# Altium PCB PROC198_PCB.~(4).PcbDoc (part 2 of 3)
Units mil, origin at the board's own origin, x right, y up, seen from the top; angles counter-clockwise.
Board outline 858.22 x 1632.74 mil, 4 copper layers (Top Layer, L2_GND1, L3_PWR1, Bottom Layer), stack 54.546 mil thick; 116 components, 64 nets, 355 pads, 1018 vias.
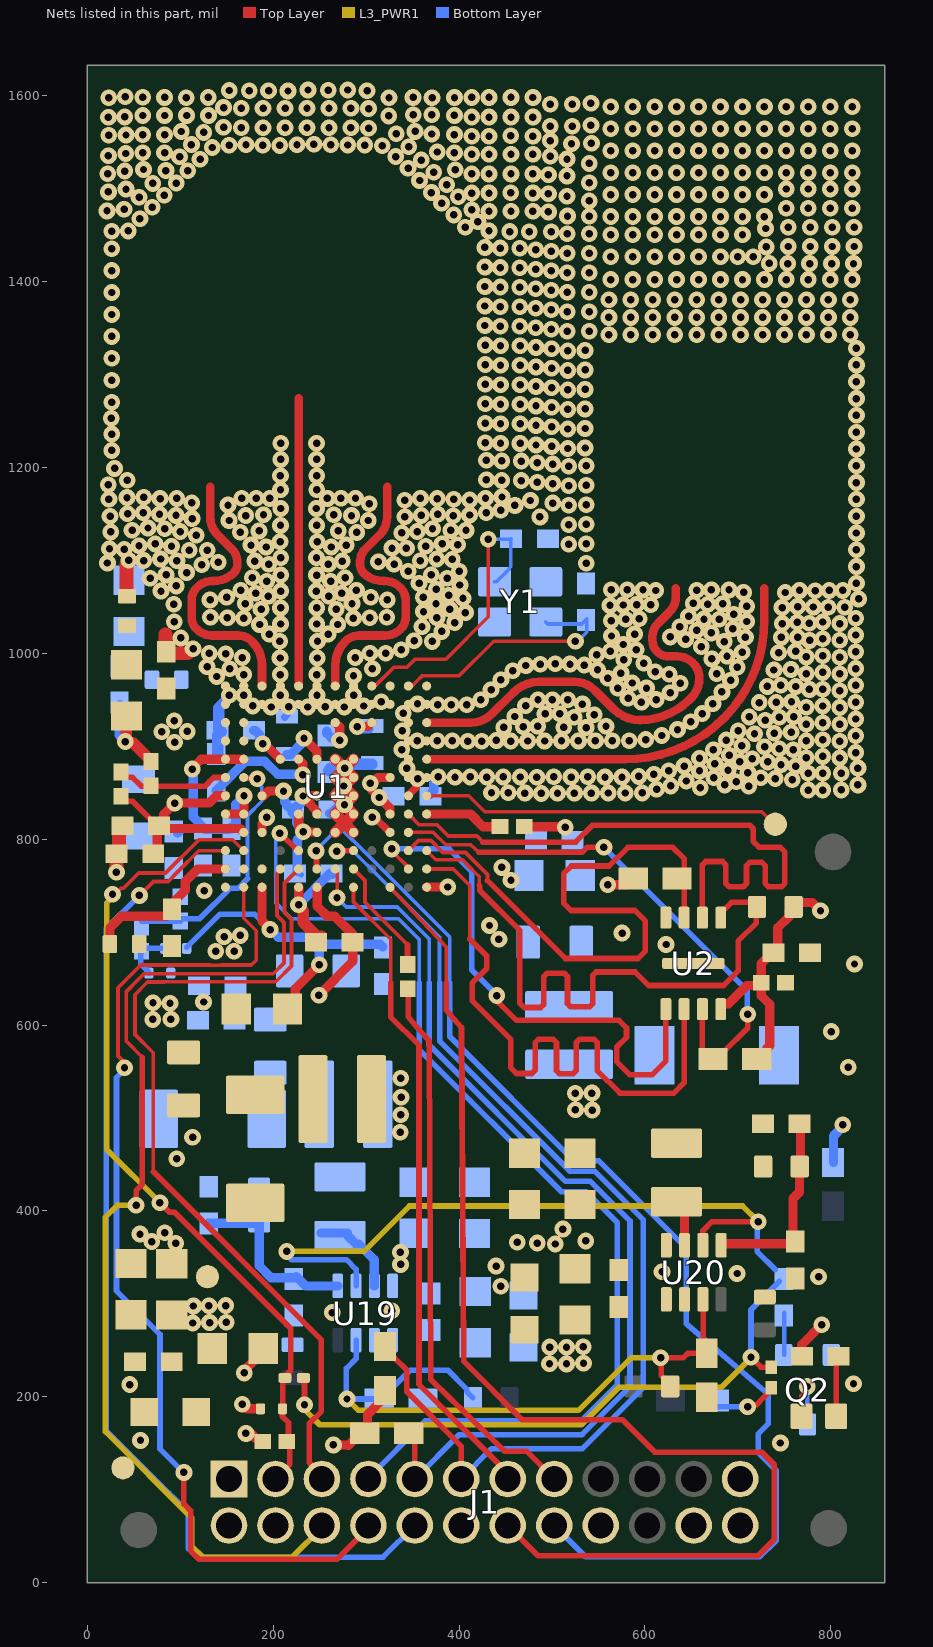
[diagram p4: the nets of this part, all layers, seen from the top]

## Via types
v1: diameter 18, hole 8, Top Layer to Bottom Layer, tented both sides, 1018 vias

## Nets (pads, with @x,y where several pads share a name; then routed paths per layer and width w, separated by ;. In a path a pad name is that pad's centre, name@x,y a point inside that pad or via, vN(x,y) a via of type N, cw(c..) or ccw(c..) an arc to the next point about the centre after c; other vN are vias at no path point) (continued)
GND: C3.2 C4.2 C5.2 C6.2 C7.2 C8.2 C9.1 C10.2 C11.2 C12.2 C13.2 C14.2 C15.2 C16.2 C17.1 C18.2 C19.2 C20.1 C21.2 C22.2 C23.2 C24.1 C25.2 C26.2 C27.1 C28.2 C29.2 C30.2 C31.1 C32.1 C33.1 C34.1 C35.2 C44.2 C45.2 C53.1 C56.2 C60.2 C61.1 C62.2 C66.2 C67.2 C68.1 C69.2 C72.2 C73.2 C74.2 C78.2 C79.1 C101.2 C119.2 C120.2 C128.2 C129.2 J1.12 J1.18 J1.22 J1.23 J1.24 Q2.2 R2.1 R121.1 R131.1 R178.2 R180.2 R238.1 R244.1 TP11.1 U1.A1 U1.A2 U1.A4 U1.A6 U1.A12 U1.B2 U1.B3 U1.B4 U1.B5 U1.B6 U1.B7 U1.C1 U1.C2 U1.D2 U1.E1 U1.E2 U1.E5 U1.E6 U1.E7 U1.E8 U1.E9 U1.F2 U1.F5 U1.F6 U1.F7 U1.F8 U1.F9 U1.G1 U1.G2 U1.H2 U1.H12 U1.J1 U1.J2 U1.K2 U1.K9 U1.L1 U1.L2 U1.M1 U1.M2 U1.M12 U2.4 U2.9 U19.8 U20.8 Y1.2 Y1.4 | length 968.8
  Top Layer w8: U1.B7@345.47,846.73 345.47,847.38 353.45,855.35 353.45,863.22 v1(355.36,865.14)
  Top Layer w10: C25.2@31.54,784.28 C25.2@32.08,784.28 ; v1@109.78,1002.59 112.23,1005.04 v1(113.78,1005.04) ; v1(168.95,225.69) 170.48,227.22 170.48,229.99 192.01,251.52 C60.2@193.96,251.52 ; v1(170.63,160.56) 172.16,159.03 177.78,159.03 181.58,155.23 185.07,155.23 C53.1@188.51,151.8 ; U1.K9@187.99,807.36 187.99,816.34 192.95,821.3 v1(192.95,823.45) ; v1(227.27,729.42) 227.36,729.5 U1.H12@227.36,748.31 ; U1.A12@365.33,748.48 v1@387.84,748.48 ; C31.1@470.17,813.7 470.58,813.29 513.93,813.29 v1(514.34,812.88)
  Top Layer w12: v1(40.81,905.09) 41.96,903.95 48.85,903.95 66.2,886.6 66.2,885.81 C3.2@68.47,883.54 ; v1@41.8,906.09 C23.2@41.8,922.79 ; v1(227.27,729.42) 227.27,727.79 232.32,722.75 232.32,710.38 246.96,695.73 C16.2@251.92,695.73 ; U1.F9@266.73,807.36 266.73,807.41 276.52,817.21 276.52,817.29 ; U1.F8@266.73,827.05 266.73,827.14 276.48,836.89 v1@276.48,837.09 ; U1.F5@266.73,886.1 U1.F5@266.96,886.1 ; U1.F8@266.73,827.05 276.52,817.29 ; v1@275.8,857.32 266.73,866.38 266.91,866.42 v1@276.76,876.26 ; U1.E9@286.42,807.36 276.52,817.29 ; U1.E5@286.42,886.1 286.42,885.92 276.8,876.3 v1(276.98,876.3) 276.98,876.08 286.42,866.65 U1.E6@286.42,866.42 285.77,866.42 276.63,857.28 v1(275.8,857.28) ; U1.F5@266.96,886.1 276.76,876.3 U1.F5@266.96,886.1 ; v1(275.8,857.28) 286.38,846.73 286.32,846.73 276.84,837.25 v1(276.75,837.25) v1@276.48,837.25 ; v1(275.8,857.28) 275.83,856.48 266.73,847.38 U1.F7@266.73,846.73 267,846.73 v1@276.48,837.25 ; v1@276.48,837.09 v1@276.48,837.25 ; v1@276.48,837.09 286.42,827.15 U1.E8@286.42,827.05 286.37,827.05 276.61,817.29 276.52,817.29
  Top Layer w15: v1@30.95,766.9 31.54,767.5 C25.2@31.54,784.28 ; C25.2@34.74,785.5 34.24,786 34.24,811.15 36.58,813.49 C26.2@36.93,813.49 ; C9.1@42.21,1063.01 v1@42.21,1095.41 ; 84.08,1020.07 84.08,1002.55 C19.2@84.89,1001.74 ; C19.2@85.1,1001.53 86.54,1000.09 108.01,1000.09 112.39,1004.47 v1@112.81,1004.05
  Bottom Layer w8: C22.2@212.26,931.48 214.95,934.17 214.95,940.7 v1(216.87,942.61)
  Bottom Layer w10: v1(227.27,729.42) 227.34,729.42 260.98,763.06 C45.2@262.57,763.06 ; C29.2@260.73,827.71 262.7,827.71 269.62,834.63 271.96,834.63 273.05,835.72 276.02,835.72 v1@277.11,834.63 ; v1@275.62,836.12 v1(276.75,837.25) 276.27,837.72 276.27,855.8 v1@276.74,856.27 ; C14.2@366.65,847.59 367.79,847.59 372.64,852.43 372.64,859.93 377.61,864.91 v1(377.61,867.08)
  Bottom Layer w12: C101.2@35.11,944.07 35.11,912.41 40.81,906.72 v1(40.81,905.09) ; C6.2@140.27,889.44 140.27,912.24 144.11,916.09 C4.2@144.21,916.09 ; C4.2@141.35,918.87 141.35,940.97 152.67,952.28 v1(152.67,954.99) ; C5.2@259.39,874.05 261.65,876.31 v1(276.98,876.3) ; C45.2@262.57,763.06 C45.2@262.95,763.06 ; v1(275.8,857.28) 276.09,857.57 276.09,875.41 v1(276.98,876.3) ; v1@276.98,876.92 v1(276.98,876.3) ; v1@278.05,877.64 278.24,877.45 v1@279.75,877.45 ; C18.2@306.34,880.72 283.02,880.72 v1@279.75,877.45 ; v1(276.98,876.3) 278.61,876.3 v1@279.75,877.45
  other v1: 745.83,150.25 57.18,153.02 45.52,213.14 824.43,213.91 263.48,290.6 327.68,292.74 444.88,319 786.88,329.32 699.18,332.64 618.45,334.47 439.82,340.7 337.05,342.47 336.86,355.54 503.52,364.46 462.56,366.16 484.11,365.38 536.45,367.76 511.75,380.47 96.12,456.31 113.26,479.34 818.82,554.53 800.61,593.03 125.05,624.84 825.54,665.74 622.76,686.69 575.37,698.99 125.94,744.68 387.91,748.55 31.29,764.38 488.58,849.24 434.88,850.03 453.01,849.86 470.86,849.61 505.93,849.6 524.17,849.64 542.41,849.68 560.65,849.71 578.89,849.75 597.13,849.79 775.8,852.91 791.25,852.93 811.39,853.05 612.53,853.68 659.65,855.48 627.84,857.33 711.68,856.95 685.82,858.39 829.24,858.46 698.39,861.98 644.57,862.63 758.64,863.94 740.36,865.22 673.97,866.29 724.65,866.18 395.6,866.76 412.01,867.01 429.89,866.89 447.51,867.04 465.86,866.92 483.76,866.66 501.94,867.12 520.53,866.9 538.61,867.11 557.02,866.9 575.3,866.89 593.47,867.55 609.72,869.88 710.86,871.31 775.8,870.99 791.25,871.01 811.39,871.13 625.75,873.76 658.74,873.45 689.41,874.19 343.9,876.16 829.24,876.54 642.12,878.71 762.49,878.69 746.45,880.29 675.31,881.12 702.22,883.27 732.04,883.2 658.74,887.03 715.35,886.71 773.5,887.68 809.52,887.43 791.25,889.09 690.69,890.39 826.94,893.23 673.73,896.34 759.61,896.14 338.31,896.49 744.64,897.22 728.78,899.38 704.37,900.7 354.88,905.81 376.59,905.82 392.56,905.82 409.33,905.42 424.5,905.42 440.21,906.29 455.51,905.65 473.75,905.69 491.99,905.72 510.23,905.76 528.47,905.8 546.71,905.83 564.95,905.87 583.19,905.91 773.5,905.76 809.52,905.51 600.77,907.23 687.4,906.66 791.25,907.17 826.94,911.31 617.99,911.6 717.94,913.62 739.06,913.99 757.26,915.25 338.87,916.53 700.44,916.75 635.04,918 448.04,920.33 536.66,920.15 469.04,920.99 512.58,920.45 484.47,921.54 558.1,921.65 773.5,923.84 809.52,923.59 791.25,925.25 649.38,926.41 729.53,928.1 826.94,929.39 523.88,931.19 744.65,931.14 459.98,932.06 712.13,931.61 760.12,931.88 545.34,933.89 492.58,934.84 508.49,935.02 661.65,935.18 340.08,935.61 197.68,942.3 237.05,942.3 276.42,942.3 773.5,941.92 809.52,941.67 256.24,942.61 297.51,943.34 791.25,943.33 177.9,943.39 471.55,943.68 376.85,944.57 391.72,944.66 408.39,944.72 355.3,945.55 532.71,945.47 673.15,945.68 596.25,947.32 722.88,947.03 741.3,947.21 316.27,947.79 757.71,947.85 826.94,947.47 423.34,950 484.93,950.04 500.47,950.19 516.99,950.05 612.17,950.25 581.89,951.79 168.39,955.06 207.76,955.06 247.13,955.06 286.5,955.06 627.05,957.61 682.83,958.49 809.52,959.75 434.43,960.91 777.03,961.18 791.25,961.41 570.88,962.52 601.71,962.65 731.79,964.41 762.36,964.36 746.22,965.82 826.94,965.55 586.34,968.14 638.06,967.81 692.15,970.85 445.07,971.59 560.2,973.31 139.2,975.13 286.43,975.74 168.27,977.16 207.64,977.16 247.01,977.16 626.28,977.49 677.37,978.14 773.5,978.08 809.52,977.83 574.15,978.79 611,980.27 791.25,979.49 457.76,981.39 548.97,982.14 738.81,982.12 757.11,982.64 153.37,983.54 306.77,983.36 826.94,983.63 699.24,985.12 128.8,985.46 471.95,986.95 534.75,987.44 487.24,988.41 503.61,988.77 519.37,988.46 598.85,989.37 577.33,993.17 672.09,993.99 207.39,994.97 247.33,994.97 166.55,995.48 288.17,995.48 773.5,996.16 809.52,995.91 688.35,996.83 791.25,997.57 548.05,998.4 131.26,999.93 149.07,999.6 304.04,1000.05 321.12,1000.13 704.57,1001.11 743.8,1000.54 562.69,1002.29 762.13,1002.26 826.94,1001.71 337.78,1003.92 590.48,1003.92 660.5,1007.26 576.78,1009.52 207.02,1012.9 247.7,1012.9 371.16,1012.84 685.28,1012.67 351.57,1013.55 777.15,1013.92 809.52,1013.99 643.78,1014.95 791.25,1015.65 100.58,1016.59 708.17,1017.29 746.84,1017.15 627.19,1017.67 764.29,1017.36 564.06,1018.67 826.94,1019.79 195.72,1020.79 259,1020.79 588.9,1020.73 671.3,1022.03 381.5,1023.62 655.66,1024.63 694.7,1026.39 360.12,1028.74 637.6,1028.67 185.3,1031.07 269.42,1031.07 207.94,1031.57 246.78,1031.57 747.91,1032.01 809.52,1032.07 395.49,1033.09 776.8,1032.38 93.38,1034.1 709.45,1034.27 763.85,1033.52 791.25,1033.73 563.78,1035.2 579.23,1036.84 594.02,1037.28 663.57,1036.91 679.99,1036.59 150.78,1038.2 168.41,1037.83 286.31,1037.83 303.94,1038.2 826.94,1037.87 132.47,1038.76 322.25,1038.76 376.16,1038.48 646.99,1039.99 695.72,1042 406.85,1043.87 361.72,1044.97 186.98,1047.39 267.74,1047.39 390.21,1047.44 207.93,1048.87 246.79,1048.87 747.62,1049.29 764.29,1050.32 781.3,1049.89 797.24,1049.68 815.12,1049.68 709.53,1050.76 562.44,1051.59 576.46,1052.01 93.08,1052.81 590.98,1052.5 606.27,1052.38 667.84,1052.86 683.55,1053.23 169.96,1053.53 284.76,1053.53 375.19,1053.5 651.87,1053.76 132.04,1057.5 322.68,1057.5 404.26,1059.31 829.91,1058.61 149.82,1060.49 304.9,1060.49 361.6,1060.35 194.88,1061.61 259.84,1061.61 388.76,1062.58 181.19,1064.59 273.53,1064.59 706.17,1065.58 751.06,1065.51 79.24,1067.03 208.2,1067.04 246.52,1067.04 165.17,1067.95 289.55,1067.95 563.63,1068.32 581,1068.32 597.93,1068.24 611.68,1067.65 655.91,1067.77 671.59,1068.24 690.49,1068.24 766.35,1067.68 783.23,1067.5 798.32,1067.68 812.87,1067.68 375.67,1068.76 95.81,1072.58 400.97,1073.58 356.99,1075.31 827.61,1075.3 193.02,1077.68 261.7,1077.68 67.52,1080.77 387.2,1080.77 177.39,1081.42 277.33,1081.42 208.06,1084.27 246.66,1084.27 84.69,1084.4 370.03,1084.4 106.79,1086.97 400.34,1088.3 345.43,1088.45 827.61,1093.38 123.17,1095.24 195.3,1095.81 259.42,1095.81 330.06,1095.98 21.57,1097.24 536.84,1096.98 140.99,1098.09 180.35,1099.3 274.37,1099.3 313.2,1098.54 44.68,1100.34 60.53,1099.87 96.4,1099.55 358.32,1099.55 392.72,1101.06 78.83,1101.57 375.89,1101.57 208.15,1102.8 246.57,1102.8 109.53,1110.86 129.02,1110.91 39.57,1111.87 827.61,1111.46 23.84,1112.48 327.85,1113.31 343.4,1113.02 90.55,1115.3 192.31,1114.45 262.41,1114.45 364.17,1115.3 55.61,1115.91 176.08,1116.51 278.64,1116.51 398.4,1116.82 72.98,1117.73 381.74,1117.73 518.11,1117.44 536.84,1117.98 207.37,1120.11 247.35,1120.11 117.32,1127.24 289.92,1130.13 338.23,1129.57 827.61,1129.54 25.05,1130.63 99.84,1131.06 164.6,1130.46 354.88,1131.06 184.83,1131.75 269.89,1131.75 390.91,1132.32 407.44,1132.32 48.14,1132.47 83.28,1134.08 371.44,1134.08 65.3,1134.89 207.84,1137.7 246.88,1137.7 518.11,1138.44 536.84,1138.98 152.49,1142.96 302.23,1142.96 112.69,1145.02 341.76,1147.05 487,1146.85 24.44,1147.57 170.48,1148.26 284.24,1148.26 393.75,1148.08 827.61,1147.62 95.4,1148.42 189.58,1149.23 265.14,1149.23 359.32,1148.42 411.32,1148.86 43.29,1150.24 77.62,1149.84 377.1,1149.84 60.05,1151.25 429.14,1151.44 444.9,1154.03 208.19,1155.87 246.53,1155.87 460.14,1159.19 151.36,1159.55 518.11,1159.44 536.84,1159.98 303.47,1160.94 112.4,1161.9 500.83,1161.7 341.56,1164.74 411.6,1165.05 476.83,1164.47 23.23,1165.73 394.31,1165.96 827.61,1165.7 78.23,1166.6 96.33,1166.71 166.17,1166.92 181.81,1166.92 196.38,1166.71 258.34,1166.71 272.91,1166.92 288.55,1166.92 358.39,1166.71 376.49,1166.6 428.43,1166.87 42.68,1167.61 60.66,1168.01 446.17,1168.23 207.82,1175.99 246.9,1175.99 518.11,1180.44 536.84,1180.98 22.63,1181.46 500.83,1182.7 484.03,1184.23 827.61,1183.78 42.89,1186.19 445.85,1186.06 466.91,1185.93 429.46,1186.72 207.78,1191.13 246.94,1191.13 29.29,1199.01 518.11,1201.44 536.84,1201.98 827.61,1201.86 500.83,1203.7 484.03,1205.23 445.85,1207.06 466.91,1206.93 429.46,1207.72 208.04,1208.66 246.68,1208.66 26.26,1218.38 827.61,1219.94 516.87,1220.45 535.59,1220.99 499.58,1222.7 482.79,1224.23 208.04,1226.19 246.68,1226.19 444.6,1226.07 465.67,1225.94 428.22,1226.73 26.26,1235.93 827.61,1238.02 516.87,1241.45 535.59,1241.99 499.58,1243.7 482.79,1245.23 444.6,1247.07 465.67,1246.94 428.22,1247.73 25.65,1252.87 827.61,1256.1 516.87,1262.45 535.59,1262.99 499.58,1264.7 482.79,1266.23 444.6,1268.07 465.67,1267.94 428.22,1268.73 26.35,1270.18 827.61,1274.18 516.87,1283.45 535.59,1283.99 499.58,1285.7 482.79,1287.23 444.6,1289.07 465.67,1288.94 428.22,1289.73 827.61,1292.26 26.35,1293.8 516.87,1304.45 535.59,1304.99 499.58,1306.7 482.79,1308.23 444.6,1310.07 465.67,1309.94 827.61,1310.34 428.22,1310.73 26.35,1317.42 516.87,1325.45 535.59,1325.99 499.58,1327.7 482.79,1329.23 827.61,1328.42 444.6,1331.07 465.67,1330.94 428.22,1331.73 26.35,1341.04 561.23,1342.95 584.85,1342.95 608.48,1342.95 632.1,1342.95 655.72,1342.95 679.34,1342.95 702.96,1342.95 726.59,1342.95 750.21,1342.95 773.83,1342.95 797.45,1342.95 821.07,1342.95 516.51,1346.5 540.13,1346.5 499.22,1348.75 482.42,1350.28 444.24,1352.11 465.3,1351.99 427.85,1352.77 561.23,1361.49 584.85,1361.49 608.48,1361.49 632.1,1361.49 655.72,1361.49 679.34,1361.49 702.96,1361.49 726.59,1361.49 750.21,1361.49 773.83,1361.49 797.45,1361.49 821.07,1361.49 26.35,1364.67 516.51,1367.5 540.13,1367.5 499.22,1369.75 482.42,1371.28 444.24,1373.11 465.3,1372.99 427.85,1373.77 561.23,1380.57 584.85,1380.57 608.48,1380.57 632.1,1380.57 655.72,1380.57 679.34,1380.57 702.96,1380.57 726.59,1380.57 750.21,1380.57 773.83,1380.57 797.45,1380.57 821.07,1380.57 26.35,1388.29 516.51,1388.5 540.13,1388.5 499.22,1390.75 482.42,1392.28 444.24,1394.11 465.3,1393.99 427.85,1394.77 563.23,1402.19 586.85,1402.19 610.48,1402.19 634.1,1402.19 657.72,1402.19 681.34,1402.19 704.96,1402.19 728.59,1402.19 752.21,1402.19 775.83,1402.19 799.45,1402.19 823.07,1402.19 516.51,1409.5 540.13,1409.5 26.35,1411.91 499.22,1411.75 482.42,1413.28 444.24,1415.11 465.3,1414.99 427.85,1415.77 733.83,1419.58 753.57,1419.45 777.19,1419.45 800.81,1419.45 824.44,1419.45 563.23,1426.81 586.85,1426.81 610.48,1426.81 634.1,1426.81 657.72,1426.81 681.34,1426.81 699.96,1426.81 716.59,1426.81 516.51,1430.5 540.13,1430.5 499.22,1432.75 482.42,1434.28 26.35,1435.53 444.24,1436.11 465.3,1435.99 427.85,1436.77 730.59,1437.37 754.21,1437.81 777.83,1437.81 801.45,1437.81 825.07,1437.81 563.23,1450.43 586.85,1450.43 610.48,1450.43 634.1,1450.43 657.72,1450.43 681.34,1450.43 704.96,1450.43 516.51,1451.5 540.13,1451.5 26.35,1454.15 454.53,1453.88 475.6,1453.75 499.22,1453.75 44.05,1454.57 432.21,1454.61 729.85,1457.18 406.74,1458.57 754.21,1458.43 777.83,1458.43 801.45,1458.43 825.07,1458.43 420.33,1464.44 56.61,1467.76 563.23,1470.06 586.85,1470.06 610.48,1470.06 634.1,1470.06 657.72,1470.06 681.34,1470.06 704.96,1470.06 728.59,1470.06 516.72,1470.57 540.13,1470.5 394.39,1471.76 496.2,1475 21.15,1476.07 432.24,1475.76 455.86,1475.76 479.48,1475.76 39.51,1477.88 413.52,1477.48 752.21,1479.06 775.83,1479.06 799.45,1479.06 823.07,1479.06 69.8,1480.11 381.2,1484.32 540.13,1486.81 55.63,1490.75 399.01,1491.31 516.12,1492.01 82.78,1492.88 563.23,1493.68 586.85,1493.68 610.48,1493.68 634.1,1493.68 657.72,1493.68 681.34,1493.68 704.96,1493.68 728.59,1493.68 413.62,1495.31 432.24,1495.31 479.48,1495.31 496.2,1494.55 370.26,1495.88 455.48,1495.77 22.7,1496.5 41.58,1499.61 752.21,1499.68 775.83,1499.68 799.45,1499.68 823.07,1499.68 386.71,1504.4 70.4,1505.68 95.55,1506.07 540.13,1506.36 357.49,1508.86 516.12,1513.75 496.2,1515.13 21.92,1516.16 413.62,1515.88 432.24,1515.88 455.86,1515.88 479.48,1515.88 563.23,1517.3 586.85,1517.3 610.48,1517.3 634.1,1517.3 657.72,1517.3 681.34,1517.3 704.96,1517.3 728.59,1517.3 752.21,1517.3 775.83,1517.3 799.45,1517.3 823.07,1517.3 372.83,1517.82 40.29,1519.01 108.11,1519.26 84.56,1519.52 395.88,1520.3 60.43,1520.67 345.14,1522.04 540.13,1527.19 359.28,1530.79 121.3,1531.61 516.12,1531.86 99.23,1534.47 331.95,1534.6 498.24,1534.88 22.7,1535.56 413.62,1537.01 432.24,1537.01 455.86,1537.01 479.48,1537.01 41.32,1537.89 59.51,1538.64 83.14,1538.64 394.98,1538.72 376.41,1539.5 563.23,1540.92 586.85,1540.92 610.48,1540.92 634.1,1540.92 657.72,1540.92 681.34,1540.92 704.96,1540.92 728.59,1540.92 752.21,1540.92 775.83,1540.92 799.45,1540.92 823.07,1540.92 134.27,1544.38 345.81,1545.1 317.42,1546.14 152.5,1546.89 170.71,1547.33 188.77,1546.74 206.97,1546.59 261.87,1547.21 280.08,1547.06 298.42,1546.93 111.98,1547.49 225.61,1547.35 243.81,1547.8 520.99,1548.26 542.48,1548.82 498.24,1551.83 413.62,1556.55 432.24,1556.55 455.48,1557.02 479.48,1556.55 22.96,1557.55 41.58,1557.81 59.51,1558.19 83.14,1558.19 394.98,1558.27 332.3,1559.19 370.58,1558.87 125.22,1560.55 101.01,1561.54 352.66,1561.64 302.64,1565.14 563.23,1564.54 586.85,1564.54 610.48,1564.54 634.1,1564.54 657.72,1564.54 681.34,1564.54 704.96,1564.54 728.59,1564.54 752.21,1564.54 775.83,1564.54 799.45,1564.54 823.07,1564.54 146.62,1566.19 165.52,1565.47 189.14,1565.47 212.76,1565.47 236.38,1565.47 260.01,1565.47 283.63,1565.47 498.14,1567.18 521.77,1567.18 541.87,1568.34 22.7,1576.95 40.29,1577.21 413.62,1577.13 432.24,1577.13 455.86,1577.13 479.48,1577.13 324.39,1578.31 59.51,1578.77 83.14,1578.77 106.76,1578.77 130.38,1578.77 394.98,1578.85 350.76,1579.45 370.58,1579.45 302.64,1586.26 146.62,1587.31 165.52,1586.59 189.14,1586.59 212.76,1586.59 236.38,1586.59 260.01,1586.59 283.63,1586.59 563.23,1588.17 586.85,1588.17 610.48,1588.17 634.1,1588.17 657.72,1588.17 681.34,1588.17 704.96,1588.17 728.59,1588.17 752.21,1588.17 775.83,1588.17 799.45,1588.17 823.07,1588.17 498.14,1590.8 521.77,1590.8 541.87,1591.96 22.96,1597.91 83.14,1598.24 106.41,1597.89 130.22,1598.21 324.59,1598.02 350.53,1598.22 370.91,1598.02 395.09,1598.07 413.62,1598.25 432.24,1598.25 455.86,1598.25 479.48,1598.14 40.81,1598.94 59.51,1598.36 215.94,1605.15 152.82,1605.67 174.29,1605.41 194.99,1605.41 237.41,1606.19 259.14,1605.93 280.35,1606.19 301.05,1605.41
GPADC1: C3.1 R86.2 U1.M6 | length 121
  Top Layer w6: R86.2@39.53,871.67 39.53,868.51 41.48,866.56 48.61,866.56 58.16,857.02 71.99,857.02 72.07,856.94 82.66,856.94 126.38,856.94 135.86,866.42 U1.M6@148.62,866.42
GPADC2: C78.1 R89.2 U1.L6 | length 263.6
  Top Layer w6: U1.L6@168.3,866.42 168.97,865.76 182.04,865.76 v1(182.71,865.09)
  Bottom Layer w4: 172.4,757.43 172.4,825.47 187.78,840.84 187.78,856.23 182.71,861.3 v1(182.71,865.09)
  Bottom Layer w6: R89.2@58.63,711.53 C78.1@100.01,711.53 ; C78.1@100.01,712.16 102.29,714.44 120.88,714.44 153.62,747.19 162.16,747.19 172.4,757.43
INPUT_3V3: C56.1 C60.1 C62.1 C66.1 C67.1 C69.1 C72.1 C73.1 C74.1 J1.1 J1.2 J1.4 L2.1 L7.1 R172.1 U19.1 U19.2 U20.1 U20.2 | length 42.7
  Top Layer w10: R172.1@768.67,243.59 768.67,256.13 v1@790,277.46
  other v1: 497.32,235.55 515.59,235.41 533.89,235.98 497.61,253.55 515.61,253.41 533.6,253.97 790.21,277.42 113.47,279.38 131.52,279.91 149.52,280.2 114.14,297.72 130.8,297.89 148.83,298.19
LVDS_D0_LIN_PHY_RX: J1.7 U1.H10 | length 1169.1
  Top Layer w4: v1(207.18,806.45) v1@207.28,806.45 ; U1.H10@226.05,787.68 U1.H10@227.36,787.68
  Top Layer w6: v1@207.28,806.45 U1.H10@226.05,787.68
  Bottom Layer w4: v1(207.18,806.45) 207.18,802.66 202.87,798.35 202.87,731.34 219.8,714.42 334.9,714.42 357.03,692.29 357.03,645.43
  Bottom Layer w6: J1.7@302.43,111.54 302.43,112.8 363.65,174.02 531.45,174.02 570.21,212.78 570.21,387.43 536.81,420.84 509.98,420.84 357.03,573.79 357.03,645.43
LVDS_D1_XDS_UARTA_RX_CAN_RX: J1.6 U1.J11 | length 1119.2
  Top Layer w4: 59.08,565.44 42,582.53 42,636.15 54.42,648.85 60.88,655.31 61.91,655.32 82.66,655.32 200.16,655.32 211.67,666.83 211.67,710.31 204.17,717.81 204.17,762.91 207.67,766.41 U1.J11@207.67,767.99
  Top Layer w6: v1(52.43,406) 52.43,421.83 59.08,428.48 59.08,565.44
  L3_PWR1 w6: v1(52.43,406) 32.22,406 19.48,393.26 19.48,162.59 112.23,69.84 112.23,39.43 124.25,27.41 220.47,27.41 252.43,59.37 J1.6@252.43,61.54
LVDS_D2_XDS_UARTA_TX_CAN_TX: J1.8 U1.L12 | length 1100.1
  Top Layer w4: v1(39.97,554.13) 39.97,559.67 33,566.65 33,640.17 57.37,664.54 131.84,664.54 131.89,664.49 144.31,664.49 144.36,664.54 176.41,664.54 181.67,669.8 181.67,701.58 168.3,714.95 U1.L12@168.3,748.31
  Top Layer w6: v1(103.89,118.64) 103.89,84.66 111.21,77.34 111.21,34.28 120.44,25.04 254.82,25.04 268.69,25.04 278.5,34.85 302.43,58.78 J1.8@302.43,61.54
  Bottom Layer w6: v1@39.82,551.87 31.35,543.4 31.35,313.99 78.18,267.16 78.18,144 103.54,118.64 v1(103.89,118.64)
LVDS_FRCLK_HOST_CLK_TP: J1.10 U1.M10 | length 1128.8
  Top Layer w4: v1(56.01,739.51) 71.06,754.55 82.66,754.55 86.98,754.55 97.55,765.11 97.55,765.41 119.83,787.68 U1.M10@146.9,787.68
  Top Layer w6: U1.M10@146.9,787.68 U1.M10@148.62,787.68
  Bottom Layer w6: v1(56.01,739.51) 20.35,703.84 20.35,163.24 87.64,95.95 87.98,95.95 91.31,92.63 91.36,92.58 108.73,75.21 108.73,36.76 118.07,27.41 318.3,27.41 J1.10@352.43,61.54
MODE: R3.1 R5.1 R238.2 R244.2 U19.3 U20.3 | length 745.8
  Top Layer w6: R5.1@627.16,211.2 627.16,213.17 617.35,222.98 617.35,241.58 v1(616.8,242.13) 641.47,242.13 646.19,246.85 R244.2@659.06,246.85 ; R244.2@662.59,250.78 U20.3@662.59,304.47 ; R244.2@663.55,254.26 659.06,249.76 663.61,249.76 R244.2@666.52,246.85
  L3_PWR1 w6: v1(279.39,197.6) 291.62,185.37 528.56,185.37 585.42,242.24 v1@616.69,242.24
  Bottom Layer w6: U19.3@289.15,261.03 289.15,240.99 278.68,230.51 278.68,198.31 v1(279.39,197.6) 313.65,197.6 R238.2@314.01,197.23 317.95,197.23 326.76,206.05 326.76,208.12 347.17,228.53 387.9,228.53 408.1,208.33 408.1,205.76 R3.1@414.94,198.92
NetC2_2: C2.2 R1.1 R2.2 U20.5 | length 208.4
  Top Layer w10: U20.5@682.02,363 682.02,363.94 682.93,364.84 R2.2@759.27,364.84 ; R2.2@759.43,365 759.43,413.47 766.34,420.39 R1.1@766.34,447.1 ; R1.1@767.35,448.32 C2.2@767.35,493.2
NetC100_2: C100.2 R119.1 R121.2 U19.5 | length 194.8
  Bottom Layer w10: C100.2@130.45,386.68 R119.1@184.93,386.68 184.93,340.99 197.72,328.2 223.38,328.2 224.68,329.5 234.89,319.3 U19.5@269.47,319.3
NetD3_1: D3.1 Q2.3 | length 75.5
  Top Layer w4.8: D3.1@768.43,179 768.43,201.17 774.79,207.53 v1(774.79,211.07)
  Bottom Layer w4.8: v1(774.79,211.07) 774.79,170.52 Q2.3@774.97,170.35
NetD3_2: D3.2 R172.2 | length 66.1
  Top Layer w6: D3.2@805.84,179 R172.2@805.84,245.07
NetQ2_1: Q2.1 R179.1 | length 45
  Bottom Layer w4.8: Q2.1@749.71,245.47 R179.1@749.71,290.5
NetR67_1: R67.1 R89.1 R131.2 | length 55.2
  Bottom Layer w6: R89.1@58.33,679.47 61.37,682.51 82.66,682.51 R67.1@83.28,682.57 ; R89.1@58.77,678.52 57.59,679.7 57.59,665.45 66.17,656.87 R131.2@66.17,655.89
NetR93_2: R93.2 U1.E11 | length 127.1
  Top Layer w4: U1.E11@286.42,767.99 298.86,755.55 298.86,732.07 344.54,686.4
  Top Layer w6: 344.54,686.4 344.54,665.19 R93.2@344.67,665.07
NetU1_K11: U1.K11
NetU1_L11: U1.L11 | length 1
  Top Layer w6: U1.L11@168.3,767.99 U1.L11@169.34,767.99
PMIC_CLKOUT_LIN_PHY_TX_SOP1: J1.5 U1.H11 | length 910.4
  Top Layer w4: 70.98,442.17 70.98,570.13 51.19,589.91 51.19,632.62 63.42,645.12 64.61,646.3 66.26,646.31 82.66,646.32 202.69,646.54 203.86,647.71 219.67,663.52 219.67,713.63 212.17,721.12 212.17,752.81 U1.H11@227.36,767.99
  Top Layer w6: 70.98,442.17 251.91,261.24 251.91,184.37 238.8,171.27 238.8,129.29 252.43,115.67 J1.5@252.43,111.54
QSPI_CS: R50.2 U1.A10 U2.1 | length 698.5
  Top Layer w4: U1.A10@365.16,787.68 375.02,777.81 403.61,777.81 409.75,771.67 418.59,762.78 421.62,759.75 421.62,750.23 ; U2.1@681.58,715.54 681.58,720.4 U2.1@682.99,721.81 ; R50.2@717.8,731.99 717.94,731.85 R50.2@717.84,731.75
  Top Layer w6: 421.59,750.21 422.3,749.5 422.3,745.01 465.1,702.22 465.1,623.91 470.07,618.93 487.76,618.93 491.28,622.45 491.28,652.29 494.79,655.8 513.19,655.8 516.71,652.29 516.71,623.04 520.22,619.53 540.42,619.53 543.93,623.04 543.93,653.61 547.45,657.13 589.43,657.13 603.93,642.62 684.55,642.62 700.34,658.41 700.34,690.27 719.9,709.84 719.9,726.41 R50.2@720.63,727.13 ; U2.1@682.99,721.81 682.99,722.85 684.49,724.35 685.53,724.35 693.17,731.99 R50.2@717.8,731.99 ; R50.2@717.84,731.75 717.84,728.02 R50.2@718.27,727.59
QSPI_D0: U1.B11 U2.5 | length 587.8
  Top Layer w4: v1(327.65,789.54) 327.65,787.4 345.47,769.58 U1.B11@345.47,767.99
  Top Layer w6: v1@440.29,631.47 442.88,628.88 442.88,623.77 461.67,604.99 572.12,604.99 580.16,596.95 580.16,586.72 569.62,576.17 569.62,560.66 583.52,546.76 607.97,546.76 622.53,561.32 U2.5@622.53,617.11
  Bottom Layer w6: v1(327.65,789.54) 389.15,789.54 413.49,765.21 413.49,659.58 427.64,645.43 440.59,632.48 v1(440.59,631.77)
QSPI_D1: U1.B8 U2.2 | length 694.6
  Top Layer w4: U1.B8@345.47,827.05 356.88,815.64 376.18,815.64 388.44,803.38 419.16,803.38 425.71,796.84
  Top Layer w6: 425.71,796.84 525.39,796.84 543.37,814.82 551.45,814.82 713.1,814.82 716.61,811.3 716.61,797.58 722.74,791.45 745.33,791.45 750.58,786.2 750.58,752.36 747.06,748.85 732.84,748.85 729.33,752.36 729.33,771.58 725.81,775.09 712.83,775.09 709.32,771.58 709.32,752.36 705.8,748.85 690.49,748.85 686.97,752.36 686.97,772.48 683.46,775.99 665.41,775.99 661.9,772.48 U2.2@661.9,715.54
QSPI_D2: R44.1 U1.B10 U2.3 | length 684.8
  Top Layer w4: U1.B10@345.47,787.68 356.39,798.6 369.68,798.6 382.47,785.81 406.93,785.81 430.62,762.12 430.62,755.38
  Top Layer w6: 430.62,755.38 514.38,671.63 592.54,671.63 600.53,679.62 600.53,711.97 589.23,723.27 551.45,723.27 520.53,723.27 512.54,731.26 512.54,762.9 520.79,771.15 551.45,771.15 561.45,771.15 581.58,791.28 629.95,791.28 642.15,779.07 R44.1@642.15,765.21 ; R44.1@634.61,757.67 642.52,749.76 U2.3@642.52,715.84
QSPI_D3: R49.1 U1.B9 U2.7 | length 568.6
  Top Layer w4: U1.B9@345.47,807.36 372.23,807.36 385.6,794 412.33,794 421.03,786.17
  Top Layer w6: 421.03,786.17 532.62,786.17 537.68,791.24 555.87,791.24 v1(555.91,791.28) ; U2.7@661.9,617.11 661.9,571.13 R49.1@664.84,568.19 ; R49.1@681.85,571.43 685.22,571.43 710.61,596.83 v1(710.61,611.8)
  Bottom Layer w6: v1(555.91,791.28) 710.31,636.88 v1@710.31,612.11
QSPI_SCLK: U1.A11 U2.6 | length 694.7
  Top Layer w4: U1.A11@365.16,767.99 393.7,767.99 411.48,750.21 411.48,692.74
  Top Layer w6: 411.48,692.74 429.83,674.39 429.83,660.99 414.03,645.19 414.03,626.25 455.77,584.5 455.77,553.94 461.79,547.92 478.3,547.92 481.82,551.43 481.82,581.14 485.33,584.65 501.34,584.65 504.85,581.14 504.85,550.98 508.37,547.46 522.56,547.46 526.07,550.98 526.07,581.3 529.59,584.82 545.12,584.82 548.64,581.3 548.64,551.24 573.07,526.82 631.11,526.82 642.21,537.92 U2.6@642.21,617.11
RADAR_1P2_RF: C20.2 C24.2 C44.1 C101.1 R8.2 U1.L4 U1.M4
  other v1: 70.49,606.1 89.93,606.32 70.67,624.1 88.94,623.61 93.84,904.23 80.03,915.76 107.46,916 93.63,927.55
RADAR_1V2: C25.1 C26.1 C27.2 C28.1 C29.1 C30.1 C45.1 R7.2 R86.1 U1.C9 U1.G7 U1.G8 U1.G9 U1.H8 U1.K7 U1.L9 U1.M7 | length 512.6
  Top Layer w6: R86.1@36.21,846.23 36.21,846.06 41.48,840.79 48.82,840.79 68.21,821.4 68.21,821.22 73.34,816.09 C26.1@79.4,816.09
  Top Layer w8: v1(306.38,823.68) 308.97,823.68 325.29,807.36 U1.C9@325.79,807.36
  Top Layer w10: C25.1@75.32,781.96 75.32,807.37 C26.1@79.54,811.58 ; C26.1@77.03,814.62 77.32,814.62 82.16,819.46 82.16,826.96 v1(94.11,838.91) 131.1,838.91 138.92,846.73 U1.M7@148.62,846.73 ; C26.1@79.99,813.98 82.03,816.02 82.03,817.66 C26.1@82.66,818.29 ; C26.1@82.66,811.5 164.17,811.5 U1.L9@168.3,807.36 ; U1.K7@187.99,846.73 189.8,846.73 194.91,851.84 v1(211.05,851.84) ; U1.H8@227.36,827.05 227.43,826.98 227.43,812.96 v1(232.38,808.01) 246.97,807.44 U1.G9@247.05,807.36 ; v1@232.2,846.66 246.97,846.66 U1.G7@247.05,846.73 ; v1@232.21,846.65 246.97,829.41 246.97,827.12 U1.G8@247.05,827.05
  Bottom Layer w6: C45.1@226,765.56 C45.1@230.02,761.54
  Bottom Layer w10: v1(211.05,851.84) 212.26,850.63 212.26,840.34 214.36,838.23 214.36,836.87 C29.1@219.12,832.12 ; C29.1@220.48,832.03 220.48,828.58 C29.1@222.34,826.72 ; C29.1@225.12,835.71 226.83,835.71 230.51,839.4 230.51,844.97 v1(232.04,846.51) ; C29.1@225.44,825.87 225.44,817.11 232.38,810.18 v1(232.38,808.01) 232.95,808.01 233.01,807.95 233.01,806.48 226,799.47 C45.1@226,765.56
  other v1: 138.1,679.49 157.93,679.54 147.13,695.07 164.42,696.51
RADAR_1V4_APLL: C22.1 U1.G5 | length 55.9
  Top Layer w10: v1(233.12,908.59) 247.05,894.66 U1.G5@247.05,886.1
  Bottom Layer w10: C22.1@214.52,890.96 218.51,890.96 231.58,904.04 231.58,907.06 v1(233.12,908.59)
RADAR_1V4_SYNTH: C18.1 U1.D3 | length 31.1
  Top Layer w10: v1(290.48,921.2) 301.88,921.2 306.03,925.35 306.03,925.4 U1.D3@306.1,925.47
  Bottom Layer w10: v1(290.48,921.2) 292.64,921.2 295.31,918.54 C18.1@303.01,918.54
RADAR_1V8: C4.1 C5.1 C7.1 C8.1 C10.1 C11.1 C12.1 C13.1 C14.1 C15.1 R6.2 R67.2 U1.C6 U1.C8 U1.F3 U1.J5 U1.K12 U1.L5 U1.L8 U1.M5 U1.M8 | length 788
  Top Layer w10: v1(112.84,875.47) 112.84,876.05 122.7,885.91 168.11,885.91 U1.L5@168.3,886.1 ; U1.M8@148.62,827.05 U1.L8@168.3,827.05 168.55,827.29 v1(168.55,846.54) ; U1.K12@187.99,748.31 187.99,712.06 196.67,703.38 v1(196.67,702.73) ; v1(188.63,902.7) 190.8,902.7 206.47,887.03 206.75,887.03 U1.J5@207.67,886.1 ; C13.1@221.48,608.72 C13.1@221.82,608.38 ; C13.1@223.67,622.72 223.67,639.06 v1(249.68,665.06) ; U1.F3@266.73,925.47 271.46,920.74 v1(271.46,906.53) ; U1.C8@325.79,827.05 325.79,833.33 v1(314.23,844.88) 305.9,853.21 305.9,858.68 v1(304.37,860.21) 306.54,860.21 312.74,866.42 U1.C6@325.79,866.42
  Bottom Layer w4: R67.2@106.9,682.57 R67.2@106.9,683.55
  Bottom Layer w6: R67.2@106.9,683.55 142.71,719.37 180.03,719.37 v1(196.67,702.73)
  Bottom Layer w10: C12.1@97.3,806.78 102.14,811.63 C11.1@125.81,811.63 ; v1(112.84,875.47) 113.86,874.44 113.86,823.84 125.81,811.89 C11.1@125.81,811.63 ; C8.1@155.05,811.2 159.69,815.84 159.69,837.68 v1(168.55,846.54) ; C8.1@155.05,813.17 152.64,810.77 150.2,810.77 126.66,810.77 C11.1@125.81,811.63 ; C4.1@178.7,916.97 180.66,916.97 185.51,912.13 185.51,907.99 188.63,904.86 v1(188.63,902.7) ; v1(196.67,702.73) 197.32,702.73 205.48,694.57 240.41,694.57 249.13,685.85 ; v1(249.68,665.06) 249.68,685.3 249.13,685.85 ; C5.1@257.74,916.04 257.74,914.07 262.58,909.23 266.6,909.23 269.3,906.53 v1(271.46,906.53) ; C7.1@317.79,684.17 314.89,687.06 250.34,687.06 249.13,685.85
  other v1: 442.93,692.31 432.74,707.15 455.92,755.79 446.15,769.64
RADAR_1V_RF_OUT: C9.2 C19.1 C23.1 U1.L3 U1.M3
RADAR_3V3: C16.1 C17.2 C21.1 C34.2 C35.1 L2.2 L7.2 R4.1 R44.2 R49.2 R50.1 R73.1 R74.1 R75.1 R165.2 R175.1 TP9.1 U1.G12 U1.M11 U2.8 | length 877.5
  Top Layer w6: R44.2@591.51,757.75 R44.2@599.21,757.75 ; v1(710.44,189.16) 712.74,191.45 720.24,191.45 723.09,194.3 ; 722.96,194.44 732.57,204.05 732.57,206.41 R175.1@735.87,209.71
  Top Layer w10: C17.2@24.28,687.29 24.28,704.75 36.7,717.17 85.11,717.17 C21.1@93.01,725.07 ; C21.1@91.29,731.04 105.44,745.18 105.44,754.56 118.87,767.99 U1.M11@148.62,767.99 ; v1(166.65,191.86) 171.42,187.09 R165.2@186.42,187.09 ; U1.G12@247.05,748.31 247.32,748.04 247.32,728.01 258.37,716.95 266.33,716.95 285.78,697.5 285.78,696.73 291.16,691.36 285.55,685.76 285.55,668.55 v1(249.23,632.23) ; v1(264.84,148.22) 280.64,148.22 281.05,147.81 R74.1@289.63,156.39 ; R74.1@287.82,167.57 R74.1@294.32,161.07 ; R74.1@298.57,160.76 301.39,163.59 301.39,180.81 315.13,194.56 315.13,199.91 R73.1@321.95,206.72 ; v1(559.9,751.03) 580.73,751.03 R44.2@587.36,757.67 ; U2.8@681.58,617.11 681.58,622.12 682.49,623.03 689.99,623.03 709.53,642.57 C34.2@725.15,642.57 ; R49.2@720.44,563.94 724.96,563.94 731.19,570.16 731.19,574.68 734.28,577.77 734.28,622.47 725.15,631.59 C34.2@725.15,642.57 ; C35.1@730.72,671.8 724.99,666.07 725.15,665.91 C34.2@725.15,645.51 C34.2@725.15,642.57 ; C35.1@742.94,675.11 742.94,704.58 755.16,716.8 755.16,722.29 R50.1@760,727.13 ; R50.1@760,731.85 780.07,731.85 v1(788.91,723.01)
  Bottom Layer w6: R4.1@666.41,190.9 668.01,189.3 v1@710.3,189.3
  Bottom Layer w10: R75.1@802.83,452.49 802.83,480.69 812.75,490.62 v1(812.75,492.67)
  other v1: 95.05,365.26 69.39,367 56.69,375.13 83.18,376.41
RADAR_NRST: C53.2 J1.3 R165.1 R176.1 U1.L10 | length 901.3
  Top Layer w4: v1(27.1,740.75) 29.81,740.75 36.44,747.38 39.25,747.38 55.42,763.55 82.66,763.55 84.01,763.55 120.01,799.54 156.44,799.54 U1.L10@168.3,787.68
  Top Layer w6: v1(78.12,408.96) 88.49,398.6 93.76,398.6 218.86,273.5 218.86,228.52 216.46,226.11 216.46,222.44 214.59,222.44 210.25,218.09 210.25,187.3 R165.1@210.09,187.14 ; J1.3@202.43,111.54 202.43,111.87 217.96,127.39 C53.2@217.96,156.83 ; R165.1@210.04,187.09 210.04,178.52 216.43,172.13 C53.2@216.43,156.83
  L3_PWR1 w6: v1(27.1,740.75) 27.1,737.67 20.66,731.23 20.66,466.42 v1(78.12,408.96)
RADAR_OSC_CLKOUT: TP5.1 U1.A7 | length 390.9
  Top Layer w4: U1.A7@365.16,846.73 410.51,846.73 427.59,829.66 725.66,829.66 TP5.1@742.13,813.19
RADAR_VBGAP: C6.1 U1.H5 | length 130.6
  Top Layer w10: U1.H5@227.22,886.1 231.77,881.56 v1(231.77,869.45)
  Bottom Layer w10: C6.1@138.57,852.48 169.83,883.75 190.84,883.75 204.75,869.84 231.38,869.84 v1(231.77,869.45)
REG_1V2: C61.2 L5.2 R7.1
REG_1V8: C68.2 L6.2 R6.1
REG_OUT_1V2: C100.1 C119.1 C120.1 L1.1 L5.1 L14.2 R119.2
  other v1: 336.67,484.73 337.14,503.4 337.63,522.29 337.37,542.68
REG_OUT_1V8: C2.1 C128.1 C129.1 L6.1 L15.2 R1.2
  other v1: 525.21,508.77 543.21,508.51 524.96,526.76 542.96,526.84
REG_PG: R175.2 R176.2 R179.2 U19.6 U20.6 | length 1448.5
  Top Layer w6: v1@232.14,193.06 v1(233.64,191.56) 233.64,219.13 R176.2@232.51,220.26 ; U20.6@662.34,363 662.34,378.68 672.16,388.51 v1(721.98,388.51) ; v1(714.13,242.61) 724.86,231.88 R175.2@735.75,231.88
  L3_PWR1 w6: v1(214.47,356.45) 297.66,356.45 346.56,405.35 705.14,405.35 v1(721.98,388.51) ; v1@233.5,189.46 233.5,186.53 250.09,169.93 531.74,169.93 572.04,210.23 682.32,210.23 v1@714.13,242.05
  Bottom Layer w6: v1(214.47,356.45) 217.08,350.16 219.68,347.56 278.73,347.56 289.15,337.14 U19.6@289.15,319.3 ; v1(714.13,242.61) 714.13,293.67 R179.2@744.77,324.31 ; v1(721.98,388.51) 720.67,387.21 720.67,356.54 R179.2@740.25,336.96
REG_RF_1V2: C79.2 L1.2 R8.1
RX1: U1.K1 | length 309.6
  Top Layer w9.3: 132.18,1179.36 132.18,1146.86 ccw(c159.62,1146.86) 140.21,1127.45 157.59,1110.08 cw(c139.09,1097.75) 161.22,1095.67 ; 135.19,1077.94 ccw(c135.19,1053.27) 117.75,1070.71 ccw(c131.14,1057.32) 112.2,1057.32 112.2,1038.7 ccw(c129.64,1038.7) 117.31,1026.37 ccw(c134.75,1043.82) 134.75,1019.15 162.11,1019.15 cw(c162.11,997.74) 177.24,1012.88 cw(c151.3,986.93) 187.99,986.93 U1.K1@187.99,964.84 ; 135.19,1077.99 ccw(c136.86,1107.16) 157.52,1086.5 ccw(c148.36,1095.66) 161.32,1095.66
RX2: U1.H1 | length 309.7
  Top Layer w9.3: U1.H1@227.36,964.84 227.36,1274.56
RX3: U1.F1 | length 309.6
  Top Layer w9.3: U1.F1@266.73,964.84 266.73,986.93 cw(c303.42,986.93) 277.48,1012.88 cw(c292.61,997.74) 292.61,1019.15 319.97,1019.15 ccw(c319.97,1043.82) 337.41,1026.37 ccw(c325.08,1038.7) 342.52,1038.7 342.52,1057.32 ccw(c323.58,1057.32) 336.97,1070.71 ccw(c319.53,1053.27) 319.53,1077.94 ; 293.4,1095.66 ccw(c306.36,1095.66) 297.19,1086.5 ccw(c317.86,1107.16) 319.53,1077.99 ; 293.5,1095.67 cw(c315.63,1097.75) 297.13,1110.08 314.51,1127.45 ccw(c295.1,1146.86) 322.54,1146.86 322.54,1179.36
SW2: L14.1 U19.7 | length 98.9
  Bottom Layer w10: L14.1@251.78,376.36 279.96,376.36 279.96,373.52 289.28,364.2 292.12,364.2 308.7,347.62 308.7,319.43 U19.7@308.84,319.3
SW3: L15.1 U20.7 | length 50.5
  Top Layer w10: L15.1@634.01,409.91 642.65,401.27 U20.7@642.65,363
TX1: U1.A3 | length 482
  Top Layer w9.3: U1.A3@365.16,925.47 412.84,925.47 ccw(c412.84,957.22) 435.28,934.77 458.49,957.98 cw(c485.98,930.49) 485.98,969.36 524.34,969.36 cw(c524.34,938.76) 545.98,960.4 566.45,939.93 ccw(c594.71,968.2) 594.71,928.22 ccw(c594.71,1003.56) 647.98,950.29 650.04,952.35 ccw(c629.43,972.97) 658.58,972.97 ccw(c634.83,972.97) 634.83,996.72 625.64,996.72 cw(c625.64,1014.33) 608.02,1014.33 608.02,1017.95 cw(c627.6,1017.95) 613.76,1031.79 626.22,1044.26 ccw(c609.06,1061.42) 633.33,1061.42 633.33,1069.92
TX2: U1.A5 | length 482.9
  Top Layer w9.3: U1.A5@365.16,886.1 578.79,886.1 ccw(c578.79,1035.86) 728.54,1035.86 728.54,1069.92
VPP_1P7: C31.2 U1.A8 | length 80.6
  Top Layer w10: U1.A8@365.16,827.05 412.22,827.05 425.73,813.53 C31.2@440.13,813.53
XDS_DCA_LP_RS232_RX: J1.9 R74.2 U1.F11 | length 1061.3
  Top Layer w4: U1.F11@266.73,767.99 266.73,766.41 269.02,764.13 269.02,737.39 v1(268.67,737.04)
  Top Layer w6: R74.2@345.81,160.76 352.43,154.14 J1.9@352.43,111.54
  Bottom Layer w4: v1(268.67,737.04) 278.56,727.15 333.48,727.15 368.03,692.6 368.03,645.43
  Bottom Layer w6: J1.9@352.43,111.54 400.23,159.34 532.33,159.34 583.98,210.99 583.98,389.22 541.36,431.84 514.53,431.84 368.03,578.34 368.03,645.43
XDS_DCA_LP_RS232_TX: J1.11 R73.2 U1.E10 | length 1170.7
  Top Layer w6: v1(268.55,787.14) 268.82,787.41 286.15,787.41 U1.E10@286.42,787.68 ; R73.2@321.95,253.97 321.95,250.03 330.76,241.22 331.15,241.22 343.76,228.61 343.76,205.4 402.43,146.73 J1.11@402.43,111.54
  Bottom Layer w4: v1(268.55,787.14) 286.2,787.14 314.81,758.54 379.03,694.32 379.03,645.43
  Bottom Layer w6: 379.03,645.43 379.03,582.9 519.09,442.84 545.92,442.84 598.35,390.41 598.35,209.8 532.74,144.2 435.08,144.2 J1.11@402.43,111.54
XDS_DCA_TCK: J1.14 U1.C12 | length 1308.5
  Top Layer w4: U1.C12@325.79,748.31 386.1,684.2 386.1,645.43
  Top Layer w6: 386.1,645.43 386.1,616.01 402.64,597.38 402.65,595.12 404.9,238.31 467.9,175.31 575.74,175.31 610.75,140.3 725.75,140.3 739.21,126.84 739.21,46.55 721.64,28.98 484.99,28.98 J1.14@452.43,61.54
XDS_DCA_TDI: J1.16 U1.G11 | length 1306.8
  Top Layer w6: v1(246.16,787.39) 246.6,786.94 246.6,768.44 U1.G11@247.05,767.99
  Bottom Layer w4: v1@245.74,787.81 266.58,808.65 275.7,808.65 285.2,799.15 285.51,799.15 318.12,766.54 390.03,694.63 390.03,645.43
  Bottom Layer w6: v1(246.16,787.39) v1@248.46,789.68 ; 390.03,645.43 390.03,587.45 523.64,453.84 550.47,453.84 644.6,359.71 644.6,278.76 646.36,277 646.52,276.84 732.91,202.5 732.91,171.11 721.84,160.04 721.84,140.1 741.34,120.6 741.34,45.59 723.41,27.66 536.31,27.66 J1.16@502.43,61.54
XDS_DCA_TDO_SOP0: J1.15 R93.1 | length 605.8
  Top Layer w6: R93.1@344.67,639.08 345.16,638.59 345.16,608.86 354.58,597.73 354.64,597.66 367.87,583 367.87,580.54 369.61,220.97 369.62,218.5 371.39,216.72 448.88,141.55 472.42,141.55 J1.15@502.43,111.54
XDS_DCA_TMS: J1.13 U1.E12 | length 705.5
  Top Layer w4: U1.E12@286.42,748.31 286.42,732.43 326.43,692.42 326.43,645.43
  Top Layer w6: 326.43,645.43 326.43,608.88 356.87,578.44 356.87,213.4 452.43,117.84 J1.13@452.43,111.54
XTALM: C33.2 U1.B1 Y1.1 | length 277.4
  Top Layer w4: U1.B1@345.47,964.84 349.45,964.84 353.97,969.36 353.97,969.48 360.52,976.03 400.32,976.03 437.39,1013.1 v1(525.25,1013.1)
  Bottom Layer w4: Y1.1@493.34,1033.76 495.44,1031.66 531.91,1031.66 537.37,1037.11 537.37,1022.8 527.67,1013.1 v1(525.25,1013.1)
XTALP: C32.2 U1.D1 Y1.3 | length 318.4
  Top Layer w4: U1.D1@306.1,964.84 309.67,964.84 329.88,985.05 343.99,985.05 352.56,993.63 385.82,993.63 431.52,1039.33 v1(431.52,1122.69)
  Bottom Layer w4: v1(431.52,1122.69) C32.2@455.61,1122.69 ; Y1.3@438.22,1077.07 440.16,1077.07 453.91,1090.81 453.91,1091.45 455.61,1093.16 C32.2@455.61,1122.69 ; C32.2@456.13,1123.2 C32.2@455.61,1122.69
pads on no net: FID1.1 FID2.1 FID3.1 FID4.1 FID5.1 FID6.1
